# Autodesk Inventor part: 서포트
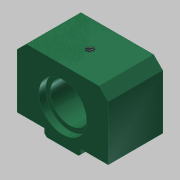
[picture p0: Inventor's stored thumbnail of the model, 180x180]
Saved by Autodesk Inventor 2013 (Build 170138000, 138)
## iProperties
Created: 2019-04
Part Number: 서포트
Material: 알루미늄 6061
Document SubType Name: Modeling
Designer: mduedu
Density: 1 g/cm^3
Author: mduedu
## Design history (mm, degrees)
sketch "스케치1"
  geometry: L1 (3, 20)-(31, 20); L2 (31, 20)-(31, -20); L3 (31, -20)-(3, -20); L4 (0, -8)-(0, 8); L5 (0, 8)-(3, 8); L6 (3, 8)-(3, 20); L7 (0, 0)-(31, 0); L8 (0, -8)-(3, -8); L9 (3, -8)-(3, -20); 1 further point
  constraints: 18 end point, 3 symmetric about line, 2 horizontal, 2 midpoint, 2 parallel, 2 perpendicular, 1 coincident
  dimensions: "d3" = 31 distance between parallel lines of L4 L2; "d5" = 16 distance of L4.start L4.end; "d6" = 40 distance between parallel lines of L3 L1; "d7" = 3 distance between parallel lines of L4 L9
extrude "돌출1" new body sketch "스케치1" distance "d8" = 24; taper "d9" = 0 deg
chamfer "모따기1" distance "d10" = 4; stored, may be unused: second distance "d11" = 2, angle "d12" = 45 deg
chamfer "모따기2" distance "d13" = 1; stored, may be unused: second distance "d14" = 2, angle "d15" = 45 deg
sketch "스케치2"
  geometry: L1 (7, 0)-(-7, 0) reference; L2 (20, 3)-(8, 3) reference; 3 further points
  constraints: 1 midpoint, 1 vertical alignment
  dimensions: "d24" = 12 distance from line of point (0, 15) L2
hole "구멍1" sketch "스케치2" at (0, 15) diameter "d17" = 17; stored, may be unused: countersink angle "d21" = 90 deg, drill point angle "d23" = 118 deg; dims "d18" = 6, "d19" = 21, "d20" = 3, "d22" = 8
sketch "스케치3"
  geometry: L1 (0, 32)-(0, 0) reference; 3 further points
  constraints: 1 horizontal alignment, 1 midpoint
  dimensions: "d25" = 12 distance from line of point (12, 16) L1
hole "구멍2" sketch "스케치3" at (12, 16) diameter "d26" = 3.242; stored, may be unused: countersink angle "d30" = 90 deg, drill point angle "d32" = 118 deg; dims "d27" = 6, "d28" = 21, "d29" = 3, "d31" = 8
sketch "스케치4"
  geometry: L1 (0, -8)-(24, -8); L2 (24, 0.5)-(24, -16.5) reference; L3 (0, -28)-(0, -24) reference; 4 further points
  constraints: 2 end point, 2 symmetric about line, 1 horizontal, 1 horizontal alignment, 1 midpoint
  dimensions: "d33" = 6 distance from line of point (6, -22) L3; "d34" = 12 distance of point (18, -22) point (6, -22); "d35" = 28 distance of point (6, 6) point (6, -22); "d36" = 14 distance from line of point (6, -22) L1 (derived)
hole "구멍3" sketch "스케치4" at (6, -22), (18, -22), (18, 6), (6, 6) diameter "d37" = 3.242; stored, may be unused: countersink angle "d41" = 90 deg, drill point angle "d43" = 118 deg; dims "d38" = 9, "d39" = 21, "d40" = 3, "d42" = 11
node "솔리드1"
